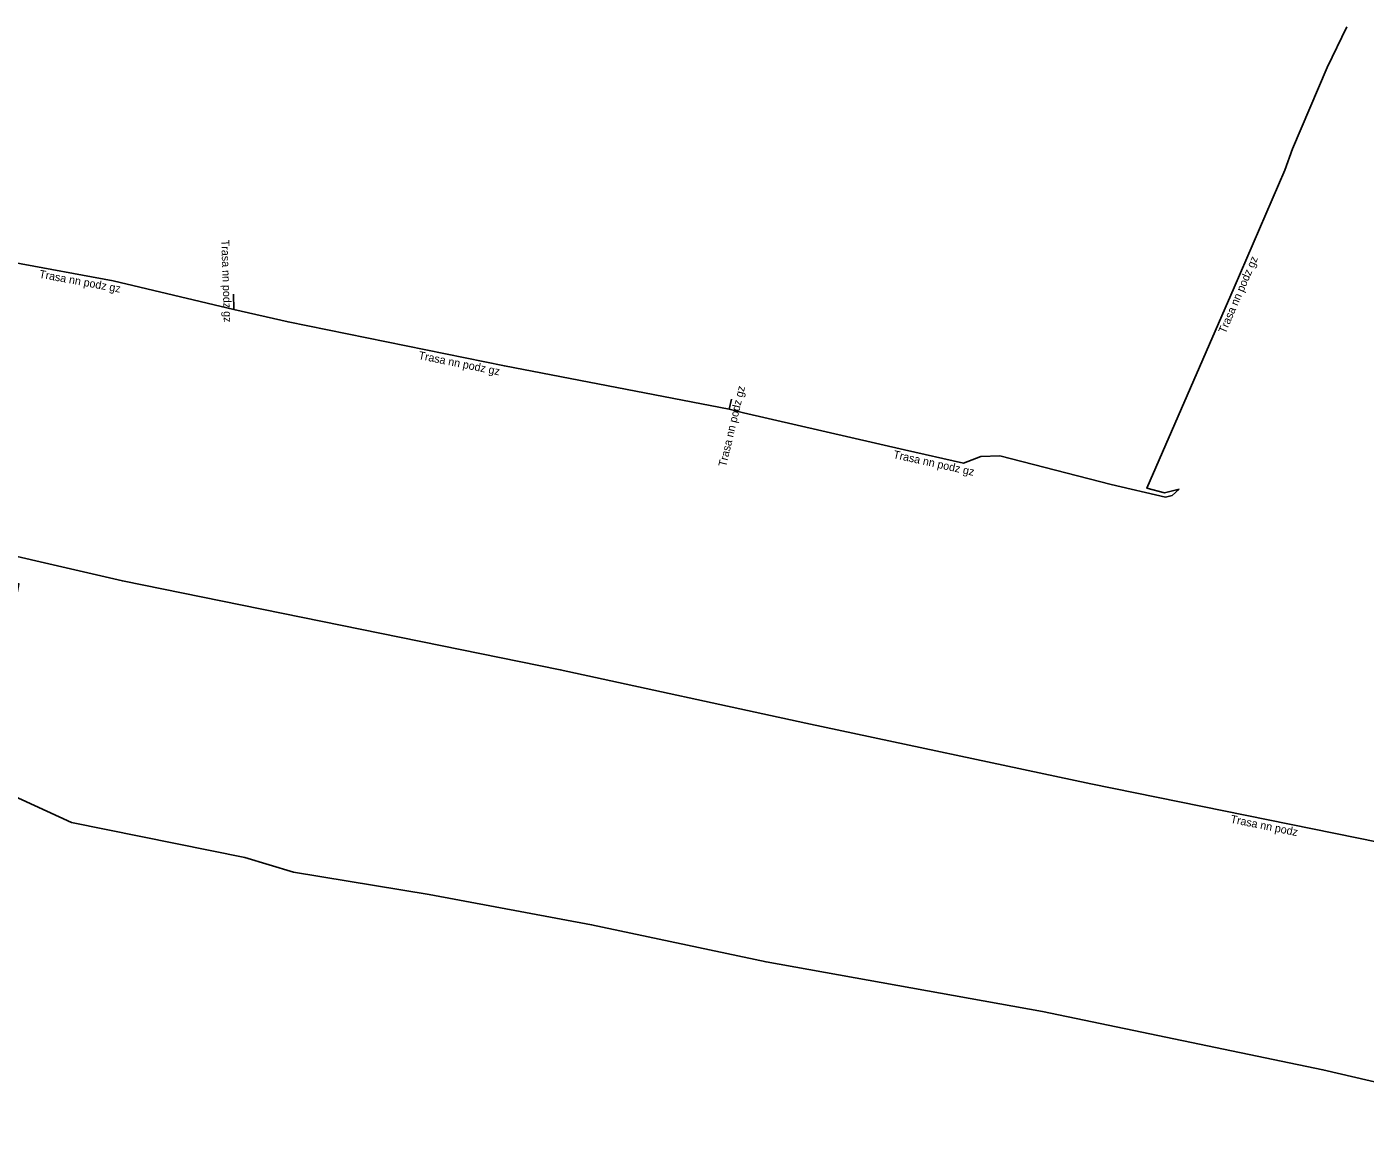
# Model space of a CAD drawing. Extents: x -687924 to -686708, y -1056742 to -1056249.
# Drawn here: x -686936.7 to -686853.1, y -1056569.5 to -1056500.7 of the extents above; entities that cross this region are included whole.
import ezdxf

# ---------------------------------------------------------------- set-up
doc = ezdxf.new("R2010")
doc.units = 0
for name, color, linetype in [('Popiskový text - Ostatní atributy Trasy', 7, 'Continuous'), ('Spojnice NN', 7, 'Continuous'), ('Spojnice VN', 7, 'Continuous')]:
    doc.layers.add(name, color=color, linetype=linetype)

msp = doc.modelspace()

# ---------------------------------------------------------------- linework, layer by layer
at = {"layer": 'Spojnice NN'}
for points in [[(-686854.21, -1056500.74), (-686855.44, -1056503.28), (-686857.61, -1056508.37), (-686858.09, -1056509.7), (-686861.25, -1056517.03), (-686866.7, -1056529.56), (-686865.61, -1056529.85), (-686864.69, -1056529.61)], [(-686940.31, -1056514.95), (-686938.31, -1056515.42), (-686937.59, -1056515.44), (-686931.28, -1056516.61), (-686923.74, -1056518.39)], [(-686923.74, -1056518.39), (-686923.77, -1056517.45)], [(-686923.74, -1056518.39), (-686920.36, -1056519.17), (-686906.84, -1056521.92), (-686892.8, -1056524.63)], [(-686892.8, -1056524.63), (-686892.65, -1056524)], [(-686892.8, -1056524.63), (-686891.9, -1056524.86), (-686881.84, -1056527.17), (-686878.15, -1056527.99), (-686877.07, -1056527.57), (-686875.89, -1056527.54), (-686868.93, -1056529.33), (-686865.53, -1056530.11), (-686865.13, -1056530.02), (-686864.69, -1056529.61)], [(-686945.918, -1056532.744), (-686942.18, -1056532.7), (-686930.7, -1056535.35), (-686903.35, -1056540.9), (-686888, -1056544.24), (-686870.2, -1056548.02), (-686850.81, -1056551.95), (-686831.84, -1056555.9), (-686818.08, -1056558.83), (-686813.22, -1056560.18), (-686808.29, -1056561.94), (-686791.49, -1056565.4), (-686770.93, -1056569.53)]]:
    msp.add_lwpolyline(points, dxfattribs=at)
at = {"layer": 'Spojnice VN'}
msp.add_lwpolyline([(-686844.685, -1056568.452), (-686855.703, -1056565.874), (-686873.231, -1056562.237), (-686890.492, -1056559.141), (-686901.391, -1056556.822), (-686911.541, -1056554.926), (-686920.025, -1056553.545), (-686923.063, -1056552.631), (-686933.877, -1056550.439), (-686939.309, -1056547.959), (-686939.059, -1056545.606), (-686937.184, -1056535.526), (-686943.273, -1056533.915), (-686947.116, -1056532.591), (-686949.244, -1056532.576), (-686950.727, -1056533.421)], dxfattribs=at)

# ---------------------------------------------------------------- texts
at = {"layer": 'Popiskový text - Ostatní atributy Trasy'}
for s, rotation, p in [('Trasa nn podz gz', 271.82797, (-686924.529, -1056514.049)), ('Trasa nn podz gz', 66.67888, (-686861.797, -1056519.941)), ('Trasa nn podz gz', 349.49552, (-686935.937, -1056516.408)), ('Trasa nn podz gz', 348.50275, (-686912.238, -1056521.485)), ('Trasa nn podz gz', 76.6075, (-686892.995, -1056528.254)), ('Trasa nn podz gz', 347.47119, (-686882.582, -1056527.67)), ('Trasa nn podz', 348.5424, (-686861.508, -1056550.445))]:
    msp.add_text(s, height=0.5, rotation=rotation, dxfattribs=at).set_placement(p)

doc.saveas('drawing.dxf')
